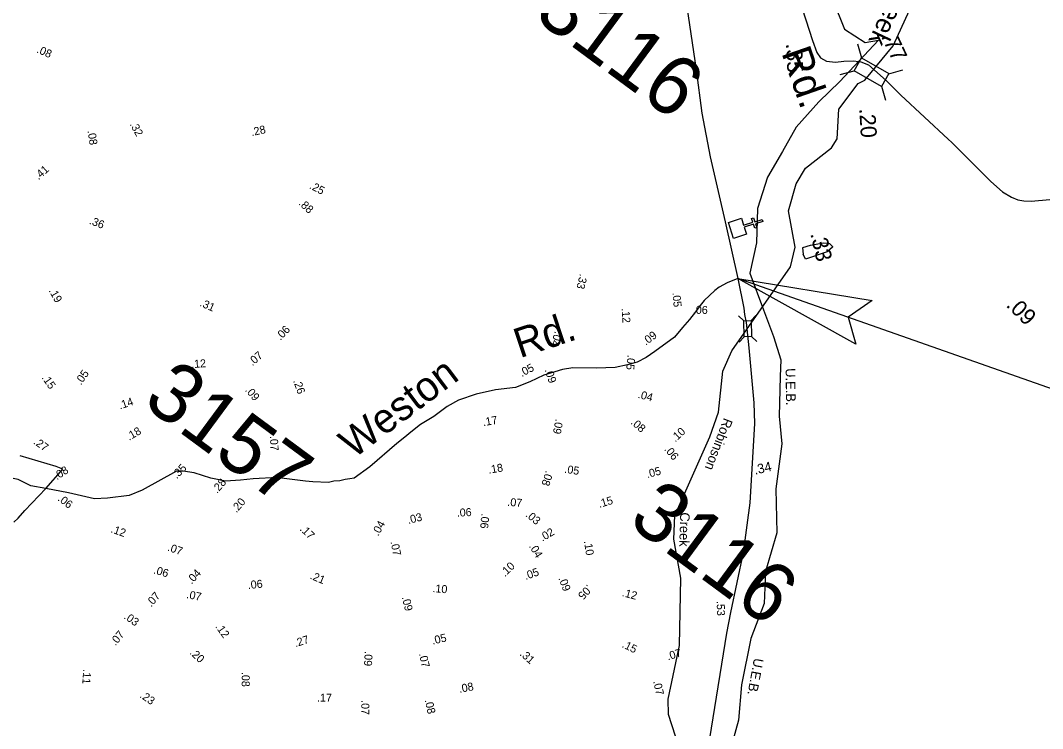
# Model space of a CAD drawing. Extents: x 945666 to 965748, y 644452 to 663300.
# Drawn here: x 953745 to 954782, y 657868 to 658587 of the extents above; entities that cross this region are included whole.
import ezdxf

# ---------------------------------------------------------------- set-up
doc = ezdxf.new("R2010")
doc.units = 0
for name, color, linetype in [('Default', 7, 'Continuous'), ('Exist Boundary Political Urban Extension UEB', 7, 'Continuous'), ('Exist Boundary Political Urban Extension UEB Label', 7, 'Continuous'), ('Exist Cultural Church CELL', 7, 'Continuous'), ('Exist Hydrographic Creek Single Shore', 7, 'Continuous'), ('Exist Hydrographic Pond Under 1500 Sq Ft', 7, 'Continuous'), ('Exist Road Secondary Mileage Tenths English Label', 7, 'Continuous'), ('Exist Road Secondary Structure Standard Bridge CELL', 7, 'Continuous'), ('Exist Road Secondary Type 51 Attributed', 7, 'Continuous'), ('Exist Road Secondary Type 51 Label', 7, 'Continuous'), ('Old_Level_1', 7, 'Continuous'), ('Prop EOT', 7, 'Continuous'), ('Prop Paved Shoulder', 7, 'Continuous'), ('Prop Terminator CELL', 7, 'Continuous'), ('Sheet Data Field CELL', 7, 'Continuous'), ('Sheet Sticker Preliminary CELL', 7, 'Continuous')]:
    doc.layers.add(name, color=color, linetype=linetype)

msp = doc.modelspace()

# ---------------------------------------------------------------- linework, layer by layer
at = {"layer": 'Default'}
for points in [[(954393.5, 658784.2), (954398, 658751.5), (954402.5, 658724.8), (954407.5, 658696.6), (954414.7, 658641.7), (954415.5, 658637.3), (954430.4, 658536.3)], [(954430.4, 658536.3), (954436.3, 658492.5), (954444.7, 658448.1), (954460.1, 658382.2), (954472.9, 658324.7)]]:
    msp.add_lwpolyline(points, dxfattribs=at)
at = {"layer": 'Exist Boundary Political Urban Extension UEB'}
for points in [[(954569.3, 658607.1), (954581.1, 658577.9)], [(954581.1, 658577.9), (954602.1, 658564.2), (954615.4, 658566.6), (954576.3, 658524.5), (954555.1, 658503.9), (954532, 658478.4), (954518, 658453.7), (954502.8, 658427.4), (954492.9, 658395.9), (954491.8, 658361), (954484.9, 658330.1), (954498.7, 658292.8), (954508.8, 658265.9), (954516.4, 658242), (954515.6, 658225.2), (954514.7, 658185.1), (954517.5, 658157), (954511.2, 658111.2), (954512.3, 658066.6), (954500.9, 658027.4), (954499.5, 657994.7), (954485.9, 657959.2), (954476.4, 657912.4), (954473.5, 657876.5), (954463.4, 657839.7)]]:
    msp.add_lwpolyline(points, dxfattribs=at)
at = {"layer": 'Exist Cultural Church CELL'}
msp.add_lwpolyline([(954476.4, 658385.8), (954478.6, 658378.7), (954488.1, 658381.7), (954486.8, 658385.6), (954488.8, 658386.3), (954490.1, 658382.3), (954497.5, 658384.6), (954498.1, 658382.6), (954490.7, 658380.3), (954491.9, 658376.3), (954489.9, 658375.7), (954488.7, 658379.7), (954479.3, 658376.7), (954481.5, 658369.6), (954468.3, 658365.4), (954463.2, 658381.6)], close=True, dxfattribs=at)
at = {"layer": 'Exist Hydrographic Creek Single Shore'}
for points in [[(954421.5, 658112.4), (954444.5, 658163.9), (954453.2, 658188.9), (954457.4, 658230.8), (954466.6, 658251.2), (954526.1, 658336.7), (954530.9, 658356.6), (954524.2, 658393.5), (954532, 658420.8), (954541.6, 658436.5), (954567.8, 658457.3), (954573.5, 658466.3), (954575.4, 658496.6), (954594.7, 658522.6), (954601.5, 658526), (954630.4, 658560.7), (954654.5, 658613.7), (954748.1, 658754.6), (954752.9, 658781.6), (954757.2, 658835.8), (954778.6, 658878.5), (954800.3, 658928.5), (954819.8, 658956.5)], [(954294, 657473.7), (954325.7, 657485.8), (954351.3, 657505.9), (954364.5, 657524.3), (954382.1, 657572.6), (954390.5, 657618.2), (954394.2, 657668.1), (954401.8, 657686.5), (954416.8, 657771.7), (954420.3, 657826.6), (954402.3, 657882.3), (954402, 657897.6), (954413.5, 657952.2), (954415, 658020.4), (954407.9, 658060.3), (954408.9, 658084.2), (954421.5, 658112.4)]]:
    msp.add_lwpolyline(points, dxfattribs=at)
at = {"layer": 'Exist Hydrographic Pond Under 1500 Sq Ft'}
for points in [[(954568.8, 658357.3), (954566.2, 658360), (954559.9, 658360.4), (954546.1, 658358.1), (954538.3, 658355.7), (954539.2, 658349.3)], [(954568.8, 658357.3), (954568.7, 658356.4), (954563.5, 658351.6), (954541.6, 658344.4), (954539.2, 658349.3)]]:
    msp.add_lwpolyline(points, dxfattribs=at)
at = {"layer": 'Exist Road Secondary Structure Standard Bridge CELL'}
for p, q in [((954594.3, 658562.8), (954598.1, 658548.6)), ((954626, 658532.5), (954640.2, 658536.4)), ((954576.5, 658531.7), (954590.7, 658535.5)), ((954618.7, 658519.8), (954622.6, 658505.6)), ((954473.3, 658286.7), (954478.7, 658281.7)), ((954491.2, 658287.3), (954486.2, 658281.9)), ((954479.3, 658265.6), (954474.2, 658260.2)), ((954486.6, 658265.8), (954492, 658260.8))]:
    msp.add_line(p, q, dxfattribs=at)
for points in [[(954598.1, 658548.6), (954626.1, 658532.6), (954618.6, 658519.5), (954590.7, 658535.5)], [(954486.2, 658281.9), (954486.7, 658265.8), (954479.1, 658265.6), (954478.7, 658281.7)]]:
    msp.add_lwpolyline(points, close=True, dxfattribs=at)
at = {"layer": 'Exist Road Secondary Type 51 Attributed'}
msp.add_line((953770.6, 658111.5), (953788.1, 658131.3), dxfattribs=at)
for points in [[(954393.5, 658784.2), (954397.2, 658783), (954420.8, 658770.3), (954438.2, 658759.4), (954447.6, 658753), (954472.2, 658732.2), (954475.6, 658728.9), (954479.4, 658724.9), (954484, 658719.4), (954487.3, 658713.7), (954508.4, 658676.7), (954534.7, 658609.7), (954548.5, 658566.2), (954553, 658554.2), (954556.8, 658548.8), (954562.6, 658545.3), (954571.7, 658544.4), (954580.4, 658545.1), (954590, 658545.5), (954595.2, 658544.9)], [(954595.2, 658544.9), (954597.6, 658544.7), (954605.4, 658541.4), (954623.4, 658525.6), (954638.2, 658510.6), (954686.2, 658466)], [(954686.2, 658466), (954689.9, 658462.6), (954729.3, 658423.2), (954741.4, 658412.7), (954750.3, 658407.1)], [(954750.3, 658407.1), (954756.9, 658404.5), (954763.1, 658403.6), (954770.4, 658403.1), (954789.3, 658404.9)], [(954472.9, 658324.7), (954462.1, 658320.3), (954453.9, 658315.8), (954449.3, 658312.5), (954438.5, 658302.5), (954434.4, 658297.2), (954429.8, 658290.7), (954423.6, 658283.1), (954416.7, 658274.9), (954408.5, 658265.3), (954388.7, 658250.7), (954379.7, 658244.4), (954370.5, 658239.8), (954360.9, 658237), (954348.4, 658234.2), (954329.5, 658233.7), (954305.4, 658234.1), (954294.8, 658232.5), (954275.9, 658226.5)], [(954472.9, 658324.7), (954478.9, 658294.7)], [(954478.9, 658294.7), (954479.7, 658288), (954481.3, 658279.9), (954484, 658254.2), (954489, 658198.6), (954489.7, 658177.4), (954484.8, 658097), (954478.2, 658046.7), (954465.5, 657985.8), (954461.3, 657964.9), (954445.7, 657868.2), (954436.6, 657812.8), (954431.3, 657780.2), (954430.3, 657774.8)], [(954275.9, 658226.5), (954261.9, 658219.7), (954247.3, 658214.2)], [(954247.3, 658214.2), (954227, 658211.7), (954207.4, 658207.2), (954189.4, 658201.2), (954177.9, 658194.9), (954172.6, 658190.6), (954164.2, 658184.8), (954150.9, 658176.4)], [(954150.9, 658176.4), (954142.7, 658170.1), (954133.3, 658162.2)], [(954133.3, 658162.2), (954126.9, 658157.3), (954099.3, 658133.6), (954083.5, 658122.1)], [(953788.1, 658131.3), (953781.1, 658133.9), (953744.8, 658144.8)], [(953770.6, 658111.5), (953755.6, 658114.4), (953742.6, 658120.6), (953737.6, 658121.7)], [(953903.3, 658129.1), (953868.5, 658109.8), (953855.2, 658104.4), (953833.4, 658101.7), (953820, 658101.2)], [(954005.8, 658122.6), (953981.2, 658121.4), (953968.1, 658119.9), (953952.9, 658118.9), (953938.1, 658122), (953921.1, 658127.4), (953909.9, 658129), (953903.3, 658129.1)], [(954083.5, 658122.1), (954079, 658121.3), (954074.5, 658120.7), (954069, 658119.4), (954062.8, 658118.9), (954057.4, 658117.7), (954041.6, 658118.3), (954034, 658119), (954012.6, 658121.7), (954005.8, 658122.6)], [(953738.4, 658077.5), (953742.8, 658081.5), (953749.5, 658089.1), (953770.6, 658111.5)], [(953820, 658101.2), (953793.7, 658107), (953770.6, 658111.5)]]:
    msp.add_lwpolyline(points, dxfattribs=at)
at = {"layer": 'Prop EOT'}
msp.add_line((954931, 658163.4), (954472.9, 658324.7), dxfattribs=at)
at = {"layer": 'Prop Terminator CELL'}
msp.add_lwpolyline([(954592.5, 658257.9), (954472.9, 658324.7), (954608.9, 658302.3), (954584.6, 658285.3)], close=True, dxfattribs=at)

# ---------------------------------------------------------------- texts
at = {"layer": 'Exist Boundary Political Urban Extension UEB Label'}
for rotation, p in [(270.8049, (954521.2, 658233.6)), (259.5793, (954489.3, 657939.9))]:
    msp.add_text('U.E.B.', height=9.8, rotation=rotation, dxfattribs=at).set_placement(p)
at = {"layer": 'Exist Road Secondary Mileage Tenths English Label'}
for s, height, rotation, p in [('.77', 16.24, 295.1322, (954617.8, 658570.6)), ('.08', 8.12, 336.1963, (953760.8, 658554.3)), ('.35', 16.24, 272.8357, (954521.6, 658563.1)), ('.20', 16.24, 273.5607, (954595.9, 658497.1)), ('.32', 8.12, 298.6935, (953855.6, 658481.3)), ('.28', 8.12, 12.6929, (953979.7, 658469.1)), ('.08', 8.12, 278.8195, (953813, 658474.6)), ('.41', 8.12, 41.5912, (953763.3, 658424.3)), ('.25', 8.12, 332.1386, (954037.5, 658416.5)), ('.88', 8.12, 317.5151, (954026.6, 658400.2)), ('.36', 8.12, 338.8831, (953814.1, 658380.4)), ('.33', 16.24, 283.1431, (954546.2, 658370.1)), ('.33', 8.12, 255.6667, (954312.7, 658329.8)), ('.19', 8.12, 299.3411, (953773.4, 658312.4)), ('.05', 8.12, 275.2505, (954406.4, 658310.3)), ('.31', 8.12, 335.7285, (953926.3, 658297.1)), ('.09', 16.24, 315.752, (954744.1, 658296.9)), ('.12', 8.12, 273.4382, (954354.9, 658294.4)), ('.06', 8.12, 359.077, (954427.1, 658288.9)), ('.06', 8.12, 45.8861, (954008.7, 658261.4)), ('.04', 8.12, 252.4381, (954287.3, 658271.6)), ('.09', 8.12, 37.105, (954379.5, 658256.4)), ('.07', 8.12, 40.8506, (953980.2, 658235.5)), ('.05', 8.12, 264.5657, (954360.9, 658247.3)), ('.12', 8.12, 3.8236, (953918.4, 658233.7)), ('.05', 8.12, 27.9412, (954253.6, 658224.6)), ('.05', 8.12, 55.2248, (953806.3, 658216)), ('.09', 8.12, 288.1148, (954276.7, 658232)), ('.15', 8.12, 305.1402, (953766.1, 658223.9)), ('.26', 8.12, 289.7152, (954021.5, 658220.8)), ('.09', 8.12, 310.5705, (953972.4, 658211.1)), ('.04', 8.12, 344.9159, (954370.8, 658203.7)), ('.14', 8.12, 18.6918, (953846, 658191.7)), ('.17', 8.12, 9.8754, (954214.6, 658174.8)), ('.18', 8.12, 30.3123, (953855.3, 658160)), ('.09', 8.12, 259.2761, (954287.9, 658182.5)), ('.08', 8.12, 318.3451, (954363.5, 658177.8)), ('.10', 8.12, 42.2468, (954409.2, 658158.2)), ('.07', 8.12, 273.1613, (953998, 658164.7)), ('.27', 8.12, 324.3885, (953757.5, 658157.5)), ('.06', 8.12, 309.0592, (954397.7, 658151.2)), ('.08', 8.12, 33.3424, (953782, 658119.9)), ('.35', 8.12, 45.4424, (953903.6, 658120.9)), ('.18', 8.12, 9.8754, (954220.2, 658126.5)), ('.05', 8.12, 351.1954, (954296.4, 658127.6)), ('.05', 8.12, 15.3887, (954381, 658122)), ('.28', 8.12, 49.1039, (953944.5, 658106)), ('.08', 8.12, 252.6598, (954278, 658130.1)), ('.06', 8.12, 322.4431, (953782.1, 658099.9)), ('.20', 8.12, 49.2227, (953964.1, 658086.3)), ('.07', 8.12, 355.4161, (954238.7, 658094)), ('.15', 8.12, 16.8674, (954332.4, 658091.8)), ('.06', 8.12, 2.8666, (954187.8, 658082.9)), ('.03', 8.12, 13.8573, (954138.5, 658075.5)), ('.06', 8.12, 265.4249, (954212.6, 658086.3)), ('.03', 8.12, 320.1769, (954256.8, 658083.8)), ('.12', 8.12, 340.6059, (953836, 658067.2)), ('.17', 8.12, 315.7094, (954027.8, 658069.8)), ('.04', 8.12, 60.7551, (954108, 658062.8)), ('.02', 8.12, 30.8676, (954274.5, 658057.5)), ('.07', 8.12, 340.6167, (953893.6, 658048.7)), ('.07', 8.12, 281.6522, (954120.4, 658057.4)), ('.04', 8.12, 301.9758, (954260.5, 658053)), ('.10', 8.12, 278.9964, (954316.6, 658058.1)), ('.06', 8.12, 343.7052, (953879.4, 658025.5)), ('.04', 8.12, 46.8962, (953918.6, 658014)), ('.10', 8.12, 43.8544, (954236.4, 658021.5)), ('.05', 8.12, 19.1422, (954257.6, 658018.7)), ('.06', 8.12, 5.7061, (953976, 658009.5)), ('.21', 8.12, 337.2321, (954038.1, 658020.2)), ('.09', 8.12, 291.1091, (954290.6, 658020.5)), ('.07', 8.12, 348.4686, (953912.9, 658000.5)), ('.10', 8.12, 354.8959, (954162.7, 658006.5)), ('.05', 8.12, 226.6238, (954320.3, 658014.6)), ('.12', 8.12, 345.1444, (954354.8, 658002.4)), ('.07', 8.12, 48.4445, (953877.5, 657990.8)), ('.09', 8.12, 283.3823, (954131.9, 658001.2)), ('.53', 8.12, 271.8025, (954451.3, 657997.3)), ('.03', 8.12, 324.7241, (953849.3, 657980.1)), ('.07', 8.12, 50.5794, (953841.4, 657951.4)), ('.12', 8.12, 305.4832, (953942.3, 657971.3)), ('.27', 8.12, 17.3461, (954024.1, 657950.5)), ('.05', 8.12, 13.293, (954163.2, 657953.1)), ('.15', 8.12, 333.6799, (954354.5, 657950.8)), ('.20', 8.12, 316.8748, (953916, 657944.2)), ('.09', 8.12, 266.683, (954094.3, 657946.6)), ('.31', 8.12, 317.7883, (954251, 657942.9)), ('.07', 8.12, 16.7856, (954401.9, 657937.1)), ('.07', 8.12, 282.8515, (954149.2, 657943.8)), ('.11', 8.12, 266.1992, (953808.7, 657928.3)), ('.08', 8.12, 269.8536, (953969.5, 657925.4)), ('.08', 8.12, 11.1718, (954190.5, 657904.1)), ('.07', 8.12, 282.8515, (954386.8, 657915.8)), ('.23', 8.12, 325.0614, (953865.4, 657900.1)), ('.17', 8.12, 358.6546, (954045.8, 657895.4)), ('.07', 8.12, 269.8536, (954090.8, 657896.8)), ('.08', 8.12, 283.063, (954155, 657896.8))]:
    msp.add_text(s, height=height, rotation=rotation, dxfattribs=at).set_placement(p)
at = {"layer": 'Exist Road Secondary Type 51 Label'}
for s, rotation, p in [('Rd.', 289.1918, (954516.8, 658553.9)), ('Rd.', 18.337, (954251.6, 658243.7)), ('Weston', 36.9236, (954082.9, 658141.2))]:
    msp.add_text(s, height=30, rotation=rotation, dxfattribs=at).set_placement(p)
at = {"layer": 'Old_Level_1'}
for s, p in [('3116', (954264.2, 658589.9)), ('3157', (953867.4, 658197.3)), ('3116', (954359.9, 658076))]:
    msp.add_text(s, height=60, rotation=323.5908, dxfattribs=at).set_placement(p)
at = {"layer": 'Prop Paved Shoulder'}
for s, height, rotation, p in [('Creek', 19.49, 244.6499, (954634.8, 658629.1)), ('Robinson', 9.74, 248.9946, (954458.8, 658183.8)), ('Creek', 9.74, 268.5062, (954414.3, 658087.4))]:
    msp.add_text(s, height=height, rotation=rotation, dxfattribs=at).set_placement(p)
at = {"layer": 'Sheet Data Field CELL'}
for s, p in [('1. DESIGN EXCEPTIONS FOR VERTICAL CURVE K VALUE', (951636, 658446)), (' AND STOPPING SIGHT DISTANCE HAVE BEEN REQUESTED', (951567.9, 658353.7))]:
    msp.add_text(s, height=87.501, rotation=323.5908, dxfattribs=at).set_placement(p)
at = {"layer": 'Sheet Sticker Preliminary CELL'}
msp.add_text('.34', height=9.74, rotation=12.7476, dxfattribs=at).set_placement((954490.2, 658125.6))

doc.saveas('drawing.dxf')
